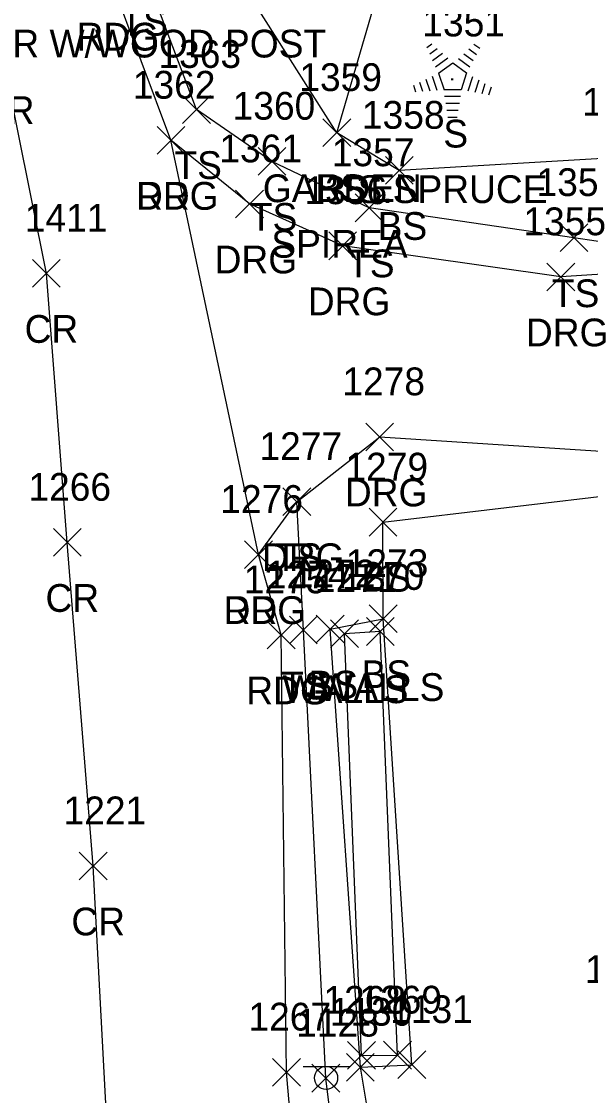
# Model space of a CAD drawing. Extents: x 1459992 to 1461532, y 647785 to 648535.
# Drawn here: x 1461385.2 to 1461426.2, y 648040.8 to 648118.2 of the extents above; entities that cross this region are included whole.
import ezdxf

# ---------------------------------------------------------------- set-up
doc = ezdxf.new("R2010")
doc.units = 0
for name, color, linetype in [('L_A', 7, 'Continuous'), ('L_C', 7, 'Continuous'), ('L_I', 7, 'Continuous'), ('L_TIC', 7, 'Continuous'), ('LAPB', 7, 'Continuous'), ('LELB', 7, 'Continuous'), ('LTC', 7, 'Continuous'), ('LWS', 7, 'Continuous'), ('P_A', 7, 'Continuous'), ('P_I', 7, 'Continuous'), ('P_TIC', 7, 'Continuous'), ('PEU', 7, 'Continuous'), ('PRC', 7, 'Continuous'), ('R_A', 7, 'Continuous'), ('R_C', 7, 'Continuous'), ('R_I', 7, 'Continuous'), ('R_TIC', 7, 'Continuous'), ('RDG', 7, 'Continuous'), ('S_I', 7, 'Continuous'), ('SSGN', 7, 'Continuous')]:
    doc.layers.add(name, color=color, linetype=linetype)

msp = doc.modelspace()

# ---------------------------------------------------------------- linework, layer by layer
at = {"layer": 'L_TIC'}
for points in [[(1461396.824, 648110.829), (1461398.824, 648112.829)], [(1461398.824, 648110.829), (1461396.824, 648112.829)], [(1461406.924, 648109.162), (1461408.924, 648111.162)], [(1461408.924, 648109.162), (1461406.924, 648111.162)], [(1461406.924, 648109.162), (1461408.924, 648111.162)], [(1461408.924, 648109.162), (1461406.924, 648111.162)], [(1461406.924, 648109.162), (1461408.924, 648111.162)], [(1461408.924, 648109.162), (1461406.924, 648111.162)], [(1461402.249, 648107.099), (1461404.249, 648109.099)], [(1461404.249, 648107.099), (1461402.249, 648109.099)], [(1461411.42, 648106.446), (1461413.42, 648108.446)], [(1461413.42, 648106.446), (1461411.42, 648108.446)], [(1461409.253, 648103.75), (1461411.253, 648105.75)], [(1461411.253, 648103.75), (1461409.253, 648105.75)], [(1461423.99, 648101.601), (1461425.99, 648103.601)], [(1461425.99, 648101.601), (1461423.99, 648103.601)], [(1461404.045, 648082.594), (1461406.045, 648084.594)], [(1461406.045, 648082.594), (1461404.045, 648084.594)], [(1461410.242, 648081.118), (1461412.242, 648083.118)], [(1461412.242, 648081.118), (1461410.242, 648083.118)], [(1461410.254, 648074.168), (1461412.254, 648076.168)], [(1461412.254, 648074.168), (1461410.254, 648076.168)], [(1461410.254, 648074.168), (1461412.254, 648076.168)], [(1461412.254, 648074.168), (1461410.254, 648076.168)], [(1461404.513, 648073.355), (1461406.513, 648075.355)], [(1461406.513, 648073.355), (1461404.513, 648075.355)], [(1461406.442, 648073.421), (1461408.442, 648075.421)], [(1461408.442, 648073.421), (1461406.442, 648075.421)], [(1461407.475, 648073.089), (1461409.475, 648075.089)], [(1461409.475, 648073.089), (1461407.475, 648075.089)], [(1461407.475, 648073.089), (1461409.475, 648075.089)], [(1461409.475, 648073.089), (1461407.475, 648075.089)], [(1461410.052, 648073.245), (1461412.052, 648075.245)], [(1461412.052, 648073.245), (1461410.052, 648075.245)], [(1461408.7, 648042.726), (1461410.7, 648044.726)], [(1461410.7, 648042.726), (1461408.7, 648044.726)], [(1461408.7, 648042.726), (1461410.7, 648044.726)], [(1461410.7, 648042.726), (1461408.7, 648044.726)], [(1461411.293, 648042.74), (1461413.293, 648044.74)], [(1461413.293, 648042.74), (1461411.293, 648044.74)], [(1461408.621, 648041.868), (1461410.621, 648043.868)], [(1461410.621, 648041.868), (1461408.621, 648043.868)], [(1461408.621, 648041.868), (1461410.621, 648043.868)], [(1461410.621, 648041.868), (1461408.621, 648043.868)], [(1461412.323, 648042.053), (1461414.323, 648044.053)], [(1461414.323, 648042.053), (1461412.323, 648044.053)], [(1461406.127, 648041.084), (1461408.127, 648043.084)], [(1461408.127, 648041.084), (1461406.127, 648043.084)]]:
    msp.add_lwpolyline(points, dxfattribs=at)
at = {"layer": 'LAPB'}
for points in [[(1461407.924, 648110.162), (1461411.912, 648123.815), (1461408.084, 648135.457), (1461400.813, 648141.208), (1461397.294, 648138.804), (1461398.931, 648128.614)], [(1461407.924, 648110.162), (1461398.363, 648125.235), (1461398.931, 648128.614)]]:
    msp.add_lwpolyline(points, dxfattribs=at)
at = {"layer": 'LELB'}
for points in [[(1461437.839, 648100.682), (1461424.99, 648102.601), (1461410.253, 648104.75), (1461403.249, 648108.099), (1461397.824, 648111.829), (1461393.938, 648122.147), (1461389.604, 648129.591), (1461386.85, 648142.876), (1461378.611, 648152.668), (1461368.623, 648163.532), (1461366.902, 648163.443), (1461362.607, 648163.899), (1461362.17, 648163.299)], [(1461478.701, 648091.669), (1461462.751, 648102.134), (1461440.785, 648105.09), (1461428.276, 648108.381), (1461412.42, 648107.446), (1461407.924, 648110.162)], [(1461409.621, 648042.868), (1461407.442, 648074.421), (1461411.254, 648075.168), (1461411.242, 648082.118), (1461429.026, 648084.238), (1461442.097, 648079.34), (1461457.906, 648073.647)], [(1461408.429, 648031.646), (1461407.127, 648042.084), (1461405.513, 648074.355), (1461405.045, 648083.594)], [(1461456.928, 647962.574), (1461441.844, 647977.438), (1461429.255, 647993.418), (1461419.691, 648013.412), (1461411.308, 648032.792), (1461409.621, 648042.868), (1461413.323, 648043.053), (1461411.254, 648075.168)]]:
    msp.add_lwpolyline(points, dxfattribs=at)
at = {"layer": 'LTC'}
for p, q in [((1461414.396, 648116.304), (1461414.751, 648116.561)), ((1461417.795, 648116.544), (1461418.214, 648116.239)), ((1461414.606, 648115.838), (1461415.135, 648116.222)), ((1461414.815, 648115.372), (1461415.519, 648115.884)), ((1461417.052, 648115.847), (1461417.732, 648115.354)), ((1461417.423, 648116.196), (1461417.973, 648115.796)), ((1461415.025, 648114.906), (1461415.903, 648115.544)), ((1461415.25, 648114.451), (1461416.261, 648115.186)), ((1461416.261, 648115.186), (1461417.258, 648114.461)), ((1461416.681, 648115.499), (1461417.491, 648114.91)), ((1461414.795, 648114.232), (1461415.126, 648113.213)), ((1461415.25, 648114.451), (1461415.637, 648113.258)), ((1461417.258, 648114.461), (1461416.867, 648113.258)), ((1461417.696, 648114.19), (1461417.358, 648113.151)), ((1461413.429, 648113.583), (1461413.581, 648113.115)), ((1461413.884, 648113.799), (1461414.096, 648113.148)), ((1461414.34, 648114.016), (1461414.611, 648113.181)), ((1461418.14, 648113.94), (1461417.853, 648113.055)), ((1461418.585, 648113.69), (1461418.348, 648112.96)), ((1461419.029, 648113.439), (1461418.842, 648112.865)), ((1461416.867, 648113.258), (1461415.637, 648113.258)), ((1461416.829, 648112.758), (1461415.684, 648112.758)), ((1461416.745, 648112.258), (1461415.757, 648112.258)), ((1461416.661, 648111.758), (1461415.83, 648111.758)), ((1461416.577, 648111.258), (1461415.902, 648111.258))]:
    msp.add_line(p, q, dxfattribs=at)
at = {"layer": 'LWS'}
for points in [[(1461409.7, 648043.726), (1461412.293, 648043.74), (1461411.052, 648074.245), (1461408.475, 648074.089)], [(1461409.7, 648043.726), (1461408.475, 648074.089)]]:
    msp.add_lwpolyline(points, dxfattribs=at)
at = {"layer": 'P_TIC'}
for points in [[(1461394.979, 648108.613), (1461396.979, 648110.613)], [(1461396.979, 648108.613), (1461394.979, 648110.613)], [(1461386.016, 648099.033), (1461388.016, 648101.033)], [(1461388.016, 648099.033), (1461386.016, 648101.033)], [(1461387.518, 648079.662), (1461389.518, 648081.662)], [(1461389.518, 648079.662), (1461387.518, 648081.662)], [(1461401.282, 648078.787), (1461403.282, 648080.787)], [(1461403.282, 648078.787), (1461401.282, 648080.787)], [(1461402.915, 648073), (1461404.915, 648075)], [(1461404.915, 648073), (1461402.915, 648075)], [(1461389.381, 648056.367), (1461391.381, 648058.367)], [(1461391.381, 648056.367), (1461389.381, 648058.367)], [(1461403.297, 648041.515), (1461405.297, 648043.515)], [(1461405.297, 648041.515), (1461403.297, 648043.515)]]:
    msp.add_lwpolyline(points, dxfattribs=at)
at = {"layer": 'PEU'}
msp.add_lwpolyline([(1461405.272, 648031.274), (1461404.297, 648042.515), (1461403.915, 648074), (1461402.282, 648079.787), (1461395.979, 648109.613), (1461391.697, 648121.078), (1461388.059, 648129.141), (1461382.567, 648140.218), (1461375.562, 648150.224), (1461367.209, 648159.2), (1461362.17, 648163.299), (1461358.126, 648158.61), (1461353.744, 648153.756)], dxfattribs=at)
at = {"layer": 'PRC'}
msp.add_lwpolyline([(1461399.102, 647801.607), (1461400.203, 647838.194), (1461399.73, 647875.765), (1461399.539, 647898.401), (1461398.446, 647928.211), (1461395.012, 647961.974), (1461394.123, 647993.813), (1461392.15, 648024.041), (1461390.381, 648057.367), (1461388.518, 648080.662), (1461387.016, 648100.033), (1461383.866, 648115.79), (1461378.351, 648129.267), (1461372.213, 648140.65), (1461365.441, 648150.969), (1461358.126, 648158.61)], dxfattribs=at)
at = {"layer": 'R_TIC'}
for points in [[(1461394.979, 648108.613), (1461396.979, 648110.613)], [(1461396.979, 648108.613), (1461394.979, 648110.613)], [(1461400.638, 648104.031), (1461402.638, 648106.031)], [(1461402.638, 648104.031), (1461400.638, 648106.031)], [(1461407.345, 648101.018), (1461409.345, 648103.018)], [(1461409.345, 648101.018), (1461407.345, 648103.018)], [(1461423.043, 648098.78), (1461425.043, 648100.78)], [(1461425.043, 648098.78), (1461423.043, 648100.78)], [(1461410.011, 648087.257), (1461412.011, 648089.257)], [(1461412.011, 648087.257), (1461410.011, 648089.257)], [(1461404.045, 648082.594), (1461406.045, 648084.594)], [(1461406.045, 648082.594), (1461404.045, 648084.594)], [(1461401.282, 648078.787), (1461403.282, 648080.787)], [(1461403.282, 648078.787), (1461401.282, 648080.787)]]:
    msp.add_lwpolyline(points, dxfattribs=at)
at = {"layer": 'RDG'}
for points in [[(1461482.007, 648090.834), (1461478.701, 648091.669), (1461462.397, 648098.679), (1461437.839, 648100.682), (1461424.043, 648099.78), (1461408.345, 648102.018), (1461401.638, 648105.031), (1461395.979, 648109.613)], [(1461402.282, 648079.787), (1461405.045, 648083.594), (1461411.011, 648088.257), (1461429.165, 648087.093), (1461442.904, 648086.026), (1461459.391, 648078.833), (1461480.341, 648074.039)]]:
    msp.add_lwpolyline(points, dxfattribs=at)
at = {"layer": 'SSGN'}
for p, q in [((1461405.499, 648042.937), (1461408.833, 648042.937)), ((1461407.146, 648042.104), (1461407.146, 648042.104))]:
    msp.add_line(p, q, dxfattribs=at)
msp.add_circle((1461407.146, 648042.104), 0.833, dxfattribs=at)

# ---------------------------------------------------------------- texts
at = {"layer": 'L_A'}
for s, p in [('TS', (1461392.347, 648117.147)), ('S', (1461415.587, 648109.095)), ('TS', (1461396.234, 648106.829)), ('GARDEN', (1461402.593, 648105.162)), ('GARDEN', (1461402.593, 648105.162)), ('BS', (1461406.365, 648105.162)), ('TS', (1461401.659, 648103.099)), ('BS', (1461410.861, 648102.446)), ('TS', (1461408.662, 648099.75)), ('TS', (1461423.399, 648097.601)), ('TS', (1461403.455, 648078.594)), ('BS', (1461409.683, 648077.118)), ('BS', (1461409.695, 648070.168)), ('BS', (1461409.695, 648070.168)), ('TS', (1461403.923, 648069.355)), ('WALLS', (1461404.018, 648069.089)), ('WALLS', (1461404.018, 648069.089)), ('BS', (1461405.883, 648069.421)), ('WALLS', (1461406.595, 648069.245))]:
    msp.add_text(s, height=2, dxfattribs=at).set_placement(p)
at = {"layer": 'L_C'}
for s, p in [('S.SPRUCE', (1461409.414, 648105.095)), ('SPIREA', (1461403.208, 648101.162)), ('SPIREA', (1461403.208, 648101.162))]:
    msp.add_text(s, height=2, dxfattribs=at).set_placement(p)
at = {"layer": 'L_I'}
for s, p in [('1351', (1461414.075, 648117.095)), ('1363', (1461395.084, 648114.829)), ('1359', (1461405.223, 648113.162)), ('1359', (1461405.223, 648113.162)), ('1359', (1461405.223, 648113.162)), ('1352', (1461425.583, 648111.381)), ('1360', (1461400.422, 648111.099)), ('1358', (1461409.727, 648110.446)), ('1357', (1461407.56, 648107.75)), ('1354', (1461422.297, 648105.601)), ('1277', (1461402.352, 648086.594)), ('1279', (1461408.541, 648085.118)), ('1273', (1461408.561, 648078.168)), ('1273', (1461408.561, 648078.168)), ('1274', (1461402.82, 648077.355)), ('1272', (1461404.749, 648077.421)), ('1271', (1461406.349, 648077.089)), ('1271', (1461406.349, 648077.089)), ('1270', (1461408.273, 648077.245)), ('1132', (1461425.783, 648048.934)), ('1268', (1461406.96, 648046.726)), ('1268', (1461406.96, 648046.726)), ('1269', (1461409.545, 648046.74)), ('1130', (1461407.409, 648045.868)), ('1130', (1461407.409, 648045.868)), ('1131', (1461411.764, 648046.053)), ('1128', (1461405.001, 648045.084))]:
    msp.add_text(s, height=2, dxfattribs=at).set_placement(p)
at = {"layer": 'LTC'}
msp.add_text('.', height=1.037, rotation=270, dxfattribs=at).set_placement((1461416.144, 648114.199))
at = {"layer": 'P_A'}
for s, p in [('RDG', (1461389.186, 648116.078)), ('CR', (1461382.299, 648110.79)), ('RDG', (1461393.467, 648104.613)), ('CR', (1461385.449, 648095.033)), ('CR', (1461386.951, 648075.662)), ('RDG', (1461399.77, 648074.787)), ('RDG', (1461401.404, 648069)), ('CR', (1461388.814, 648052.367))]:
    msp.add_text(s, height=2, dxfattribs=at).set_placement(p)
at = {"layer": 'P_I'}
for s, p in [('1362', (1461393.238, 648112.613)), ('1411', (1461385.457, 648103.033)), ('1266', (1461385.722, 648083.662)), ('1276', (1461399.534, 648082.787)), ('1275', (1461401.223, 648077)), ('1221', (1461388.255, 648060.367)), ('1267', (1461401.557, 648045.515))]:
    msp.add_text(s, height=2, dxfattribs=at).set_placement(p)
at = {"layer": 'R_A'}
for p in [(1461393.467, 648104.613), (1461399.126, 648100.031), (1461405.833, 648097.018), (1461421.532, 648094.78), (1461408.499, 648083.257), (1461402.533, 648078.594), (1461399.77, 648074.787)]:
    msp.add_text('DRG', height=2, dxfattribs=at).set_placement(p)
at = {"layer": 'R_C'}
msp.add_text('SGR W/WOOD POST', height=2, dxfattribs=at).set_placement((1461380.706, 648115.578))
at = {"layer": 'R_I'}
for s, p in [('1362', (1461393.238, 648112.613)), ('1361', (1461399.465, 648108.031)), ('1356', (1461405.597, 648105.018)), ('1355', (1461421.35, 648102.78)), ('1278', (1461408.318, 648091.257)), ('1277', (1461402.352, 648086.594)), ('1276', (1461399.534, 648082.787))]:
    msp.add_text(s, height=2, dxfattribs=at).set_placement(p)
at = {"layer": 'S_I'}
msp.add_text('1128', height=2, dxfattribs=at).set_placement((1461405.001, 648045.084))

doc.saveas('drawing.dxf')
